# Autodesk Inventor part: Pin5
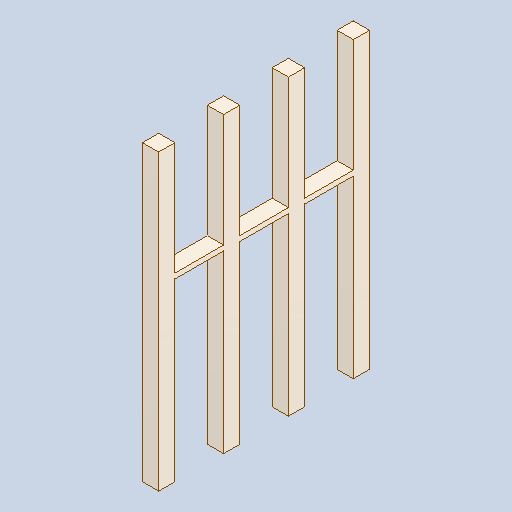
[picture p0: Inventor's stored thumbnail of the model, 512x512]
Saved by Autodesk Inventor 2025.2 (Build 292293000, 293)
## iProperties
Created: 2025-04
Part Number: Pin5
Material: Generic
Description: PART--DESC
Document SubType Name: Modeling
Designer: BennF
Density: 1 g/cm^3
Appearance: Default
Author: BennF
Revision Number: NONE
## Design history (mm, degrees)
feature "Solid"
body "Solid1"
